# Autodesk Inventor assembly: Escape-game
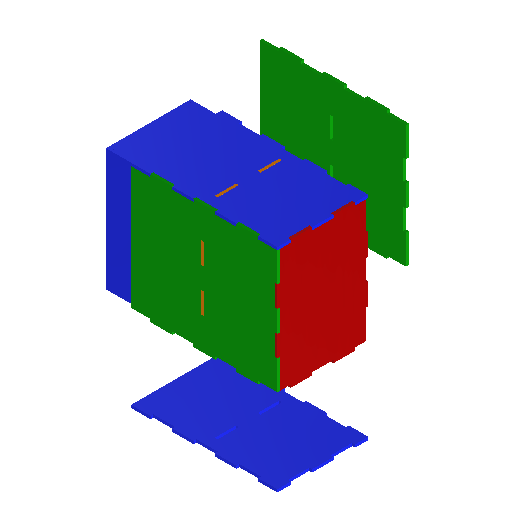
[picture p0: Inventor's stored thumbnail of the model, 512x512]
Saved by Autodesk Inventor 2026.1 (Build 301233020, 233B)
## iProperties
Created: 2023-12
Part Number: Escape-game
Document SubType Name: Assembly
Designer: bruno
Author: bruno
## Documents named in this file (4)
- M:\STI2D\IT\Escape game\Escape-game\Escape-game.iam
- M:\STI2D\IT\Escape game\Escape-game\Boite\boite_fixe.iam
- M:\STI2D\IT\Escape game\Escape-game\MotoreducteurRB35\motoreducteur_axe.ipt
- M:\STI2D\IT\Escape game\Escape-game\Boite\boite_amovible.iam
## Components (3 placed, 3 different names)
1. boite_fixe:1 [sub-assembly] — Logement:1, Placage:1, Placage:2
2. motoreducteur_axe:1 — Logement:1
3. boite_amovible:1 [sub-assembly] — Placage:1, Placage:2
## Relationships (3: Mate 2, Insert 1)
- Logement:1 [Insert]: boite_fixe:1 ↔ motoreducteur_axe:1
- Placage:1 [Mate]: boite_fixe:1 ↔ boite_amovible:1
- Placage:2 [Mate]: boite_fixe:1 ↔ boite_amovible:1
